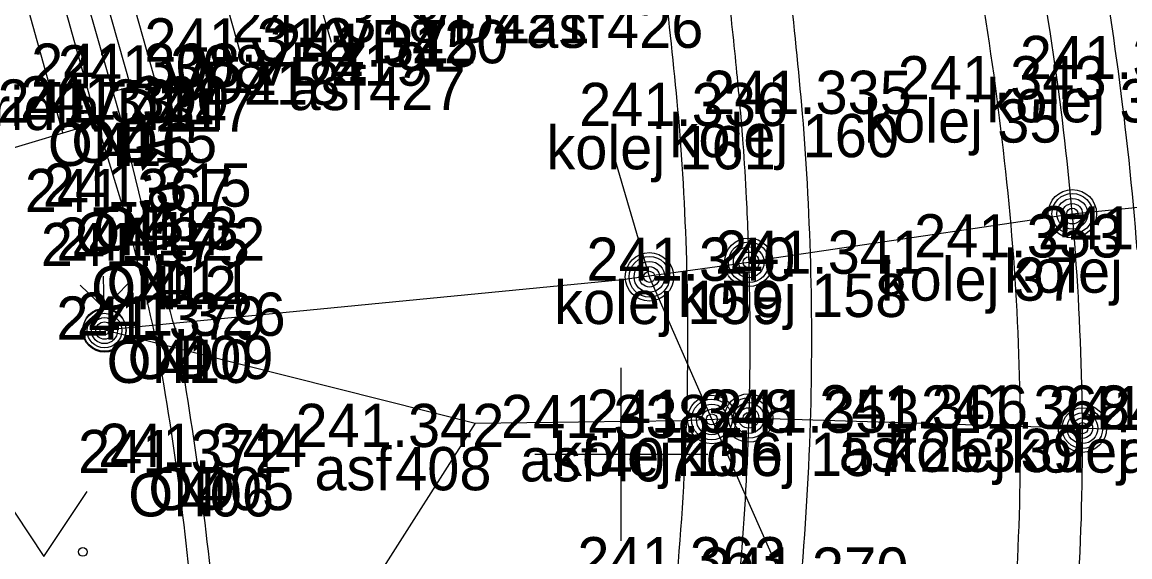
# Model space of a CAD drawing. Extents: x -599098 to -598820, y -1159597 to -1158744.
# Drawn here: x -598906.93 to -598894.12, y -1159351.19 to -1159345 of the extents above; entities that cross this region are included whole.
import ezdxf

# ---------------------------------------------------------------- set-up
doc = ezdxf.new("R2010")
doc.units = 0
for name, color, linetype in [('body', 7, 'Continuous'), ('druh pozemku stromy', 7, 'Continuous'), ('hektometrická síť', 7, 'Continuous'), ('kresba', 7, 'Continuous'), ('kódy bodů', 7, 'Continuous'), ('popisy', 7, 'Continuous'), ('tram_koleje', 7, 'Continuous'), ('tram_osa', 7, 'Continuous'), ('trol_detaily', 7, 'Continuous'), ('trol_převěsy', 7, 'Continuous'), ('trol_troljová stopa', 7, 'Continuous'), ('trol_ved sloupy konzoly', 7, 'Continuous'), ('vodorovné dopravní značení_bílé', 7, 'Continuous'), ('výšky bodů', 7, 'Continuous'), ('značky IS', 7, 'Continuous'), ('čísla bodů', 7, 'Continuous')]:
    doc.layers.add(name, color=color, linetype=linetype)

msp = doc.modelspace()

# ---------------------------------------------------------------- linework, layer by layer
at = {"layer": 'body'}
for p, q in [((-598903.354, -1159345.238), (-598903.354, -1159345.238)), ((-598904.366, -1159345.459), (-598904.366, -1159345.459)), ((-598902.918, -1159345.52), (-598902.918, -1159345.52)), ((-598894.236, -1159345.662), (-598894.236, -1159345.662)), ((-598905.676, -1159345.751), (-598905.676, -1159345.751)), ((-598905.367, -1159345.77), (-598905.367, -1159345.77)), ((-598895.649, -1159345.896), (-598895.649, -1159345.896)), ((-598897.902, -1159346.065), (-598897.902, -1159346.065)), ((-598906.065, -1159346.166), (-598906.065, -1159346.166)), ((-598905.791, -1159346.13), (-598905.791, -1159346.13)), ((-598899.327, -1159346.205), (-598899.327, -1159346.205)), ((-598905.542, -1159347.137), (-598905.542, -1159347.137)), ((-598905.749, -1159347.2), (-598905.749, -1159347.2)), ((-598905.384, -1159347.763), (-598905.384, -1159347.763)), ((-598895.459, -1159347.724), (-598895.459, -1159347.724)), ((-598905.564, -1159347.824), (-598905.564, -1159347.824)), ((-598897.805, -1159347.913), (-598897.805, -1159347.913)), ((-598899.237, -1159347.994), (-598899.237, -1159347.994)), ((-598905.385, -1159348.675), (-598905.385, -1159348.675)), ((-598905.14, -1159348.63), (-598905.14, -1159348.63)), ((-598896.55, -1159349.701), (-598896.55, -1159349.701)), ((-598895.381, -1159349.704), (-598895.381, -1159349.704)), ((-598900.24, -1159349.813), (-598900.24, -1159349.813)), ((-598899.248, -1159349.751), (-598899.248, -1159349.751)), ((-598897.814, -1159349.751), (-598897.814, -1159349.751)), ((-598902.617, -1159349.916), (-598902.617, -1159349.916)), ((-598905.134, -1159350.218), (-598905.134, -1159350.218)), ((-598904.9, -1159350.146), (-598904.9, -1159350.146))]:
    msp.add_line(p, q, dxfattribs=at)
at = {"layer": 'druh pozemku stromy'}
msp.add_lwpolyline([(-598907.18, -1159350.43), (-598906.68, -1159351.18), (-598906.18, -1159350.43)], dxfattribs=at)
msp.add_lwpolyline([(-598907.18, -1159350.43), (-598906.68, -1159351.18), (-598906.18, -1159350.43)], dxfattribs=at)
msp.add_circle((-598906.231, -1159351.129), 0.05, dxfattribs=at)
msp.add_circle((-598906.231, -1159351.129), 0.05, dxfattribs=at)
at = {"layer": 'hektometrická síť'}
for p, q in [((-598900, -1159351), (-598900, -1159349)), ((-598901, -1159350), (-598899, -1159350))]:
    msp.add_line(p, q, dxfattribs=at)
at = {"layer": 'kresba'}
for p, q in [((-598905.676, -1159345.751), (-598907.263, -1159340.087)), ((-598906.065, -1159346.166), (-598907.388, -1159341.438)), ((-598907.153, -1159341.381), (-598905.791, -1159346.13)), ((-598906.46, -1159346.285), (-598907.797, -1159341.508)), ((-598905.676, -1159345.751), (-598905.882, -1159345.81)), ((-598906.065, -1159346.166), (-598909.141, -1159347.095)), ((-598905.749, -1159347.2), (-598906.065, -1159346.166)), ((-598905.791, -1159346.13), (-598905.542, -1159347.137))]:
    msp.add_line(p, q, dxfattribs=at)
for centre, radius, start, end in [((-598877.803, -1159340.469), 28.529, 193.517, 196.6227), ((-598928.971, -1159353.713), 24.118, 12.0576, 15.6673), ((-598936.186, -1159354.477), 31.342, 4.3371, 10.6684), ((-598943.571, -1159355.491), 39.039, 4.9847, 10.1223)]:
    msp.add_arc(centre, radius, start, end, dxfattribs=at)
at = {"layer": 'tram_koleje'}
for centre, radius, start, end in [((-598957.61, -1159351.342), 59.941, 5.05089, 8.00972), ((-598962.061, -1159351.823), 62.985, 5.11744, 7.90196), ((-598930.034, -1159350.401), 36.11, 4.398, 10.9741), ((-598930.08, -1159350.399), 34.724, 4.4175, 11.0015), ((-598929.966, -1159348.675), 32.17, 358.0824, 4.6528), ((-598930.62, -1159348.676), 31.391, 358.0376, 4.5149), ((-598924.431, -1159349.857), 29.05, 356.3663, 4.2104), ((-598930.909, -1159348.603), 31.681, 350.7182, 357.9236), ((-598931.638, -1159348.556), 33.845, 350.8772, 357.9764)]:
    msp.add_arc(centre, radius, start, end, dxfattribs=at)
at = {"layer": 'tram_osa'}
for points in [[(-598908.157, -1159378.609), (-598907.552, -1159377.778), (-598906.868, -1159376.836), (-598906.259, -1159375.995), (-598905.722, -1159375.252), (-598905.236, -1159374.581), (-598903.934, -1159372.775), (-598902.701, -1159371.051), (-598901.52, -1159369.371), (-598900.942, -1159368.531), (-598900.379, -1159367.695), (-598899.817, -1159366.835), (-598899.27, -1159365.964), (-598898.407, -1159364.472), (-598897.213, -1159362.023), (-598896.143, -1159359.185), (-598895.328, -1159356.139), (-598894.957, -1159354.036), (-598894.725, -1159351.774), (-598894.664, -1159349.708), (-598894.744, -1159347.678), (-598894.942, -1159345.779), (-598895.289, -1159343.649), (-598895.717, -1159341.566), (-598895.998, -1159340.38), (-598896.298, -1159339.199), (-598896.678, -1159337.758), (-598897.069, -1159336.322), (-598897.39, -1159335.158), (-598897.753, -1159333.858), (-598898.122, -1159332.54), (-598898.277, -1159331.985), (-598898.513, -1159331.142), (-598898.836, -1159329.985), (-598899.092, -1159329.068)], [(-598901.994, -1159329.852), (-598901.845, -1159330.39), (-598901.631, -1159331.17), (-598901.437, -1159331.875), (-598901.198, -1159332.751), (-598900.91, -1159333.821), (-598900.692, -1159334.638), (-598900.522, -1159335.294), (-598900.329, -1159336.063), (-598900.132, -1159336.868), (-598899.889, -1159337.918), (-598899.746, -1159338.571), (-598899.547, -1159339.551), (-598899.39, -1159340.382), (-598899.195, -1159341.532), (-598899.02, -1159342.683), (-598898.837, -1159344.035), (-598898.771, -1159344.588), (-598898.665, -1159345.59), (-598898.593, -1159346.409), (-598898.554, -1159347.04), (-598898.521, -1159347.953), (-598898.531, -1159349.751), (-598898.642, -1159351.517), (-598898.931, -1159353.817), (-598899.252, -1159355.498), (-598899.926, -1159358.17), (-598900.833, -1159360.806), (-598901.398, -1159362.161), (-598902.424, -1159364.327), (-598904.147, -1159367.423), (-598905.388, -1159369.399), (-598906.458, -1159371.007), (-598907.174, -1159372.046), (-598907.418, -1159372.398), (-598907.811, -1159372.961), (-598908.189, -1159373.5), (-598908.527, -1159373.98), (-598908.94, -1159374.563), (-598909.247, -1159374.993), (-598909.701, -1159375.623), (-598910.021, -1159376.065), (-598910.194, -1159376.303), (-598910.561, -1159376.808)]]:
    msp.add_spline(points, degree=3, dxfattribs=at)
at = {"layer": 'trol_detaily'}
for centre, radius in [((-598894.781, -1159347.219), 0.28), ((-598894.781, -1159347.219), 0.235), ((-598894.781, -1159347.219), 0.178), ((-598894.781, -1159347.219), 0.118), ((-598894.781, -1159347.219), 0.0641), ((-598898.525, -1159347.78), 0.28), ((-598898.525, -1159347.78), 0.235), ((-598898.525, -1159347.78), 0.178), ((-598899.674, -1159347.948), 0.28), ((-598899.674, -1159347.948), 0.235), ((-598899.674, -1159347.948), 0.178), ((-598898.525, -1159347.78), 0.118), ((-598898.525, -1159347.78), 0.0641), ((-598899.674, -1159347.948), 0.118), ((-598899.674, -1159347.948), 0.0641), ((-598898.952, -1159349.597), 0.28), ((-598898.526, -1159349.58), 0.28), ((-598898.952, -1159349.597), 0.235), ((-598898.952, -1159349.597), 0.178), ((-598898.526, -1159349.58), 0.235), ((-598898.526, -1159349.58), 0.178), ((-598894.664, -1159349.698), 0.28), ((-598898.952, -1159349.597), 0.118), ((-598898.952, -1159349.597), 0.0641), ((-598898.526, -1159349.58), 0.118), ((-598898.526, -1159349.58), 0.0641), ((-598894.664, -1159349.698), 0.235), ((-598894.664, -1159349.698), 0.178), ((-598894.664, -1159349.698), 0.118), ((-598894.664, -1159349.698), 0.0641)]:
    msp.add_circle(centre, radius, dxfattribs=at)
at = {"layer": 'trol_převěsy'}
for p, q in [((-598894.781, -1159347.218), (-598891.512, -1159346.899)), ((-598898.23, -1159347.73), (-598894.781, -1159347.218)), ((-598899.99, -1159347.98), (-598898.525, -1159347.779)), ((-598898.525, -1159347.779), (-598898.23, -1159347.73)), ((-598905.98, -1159348.56), (-598899.99, -1159347.98)), ((-598905.98, -1159348.56), (-598901.69, -1159349.64)), ((-598899.3, -1159349.61), (-598898.54, -1159349.58)), ((-598898.54, -1159349.58), (-598894.25, -1159349.71)), ((-598901.69, -1159349.64), (-598906.25, -1159356.79)), ((-598901.69, -1159349.64), (-598899.3, -1159349.61)), ((-598894.25, -1159349.71), (-598891.79, -1159349.74))]:
    msp.add_line(p, q, dxfattribs=at)
at = {"layer": 'trol_troljová stopa'}
for p, q in [((-598899.67, -1159347.96), (-598900.1, -1159346.487)), ((-598898.95, -1159349.6), (-598899.67, -1159347.96)), ((-598896.7, -1159354.66), (-598898.95, -1159349.6))]:
    msp.add_line(p, q, dxfattribs=at)
at = {"layer": 'trol_ved sloupy konzoly'}
for q in [(-598906.259, -1159348.044), (-598905.99, -1159347.939), (-598905.698, -1159348.018)]:
    msp.add_line((-598905.984, -1159348.311), q, dxfattribs=at)
msp.add_circle((-598905.98, -1159348.56), 0.248, dxfattribs=at)
at = {"layer": 'vodorovné dopravní značení_bílé'}
for p, q in [((-598903.354, -1159345.238), (-598904.741, -1159340.325)), ((-598904.366, -1159345.497), (-598905.753, -1159340.584)), ((-598905.367, -1159345.77), (-598906.754, -1159340.857))]:
    msp.add_line(p, q, dxfattribs=at)
at = {"layer": 'značky IS'}
for radius in [0.25, 0.2, 0.15, 0.1, 0.05]:
    msp.add_circle((-598905.98, -1159348.57), radius, dxfattribs=at)

# ---------------------------------------------------------------- texts
at = {"layer": 'kódy bodů'}
for s, p in [('VDZ', (-598902.4, -1159345.249)), ('asf', (-598901.098, -1159345.301)), ('VDZ', (-598903.341, -1159345.479)), ('VDZ', (-598904.274, -1159345.738)), ('VDZ', (-598905.286, -1159345.959)), ('asf', (-598903.851, -1159346.02)), ('pridla', (-598907.662, -1159346.251)), ('kolej', (-598895.776, -1159346.162)), ('VDZ', (-598906.287, -1159346.27)), ('kolej', (-598897.189, -1159346.396)), ('kolej', (-598899.442, -1159346.565)), ('ON', (-598906.635, -1159346.666)), ('OD', (-598906.363, -1159346.63)), ('kolej', (-598900.867, -1159346.705)), ('OD', (-598906.114, -1159347.637)), ('ON', (-598906.319, -1159347.7)), ('kolej', (-598895.57, -1159348.132)), ('OD', (-598905.956, -1159348.263)), ('kolej', (-598896.999, -1159348.224)), ('ON', (-598906.134, -1159348.324)), ('kolej', (-598899.345, -1159348.413)), ('kolej', (-598900.777, -1159348.494)), ('ON', (-598905.955, -1159349.175)), ('OD', (-598905.712, -1159349.13)), ('asf', (-598897.483, -1159350.201)), ('kolej', (-598896.921, -1159350.204)), ('kolej', (-598895.488, -1159350.212)), ('asf', (-598894.248, -1159350.215)), ('asf', (-598901.173, -1159350.313)), ('kolej', (-598900.788, -1159350.251)), ('kolej', (-598899.354, -1159350.251)), ('asf', (-598903.55, -1159350.416)), ('ON', (-598905.704, -1159350.718)), ('OD', (-598905.472, -1159350.646))]:
    msp.add_text(s, height=0.5, dxfattribs=at).set_placement(p)
at = {"layer": 'popisy'}
msp.add_text('k.o.', height=0.5, rotation=283.8889, dxfattribs=at).set_placement((-598905.621, -1159346.402))
at = {"layer": 'výšky bodů'}
for s, p in [('241.318', (-598904.506, -1159345.238)), ('241.312', (-598905.518, -1159345.459)), ('241.315', (-598904.07, -1159345.52)), ('241.345', (-598895.388, -1159345.662)), ('241.308', (-598906.828, -1159345.751)), ('241.308', (-598906.519, -1159345.77)), ('241.343', (-598896.801, -1159345.896)), ('241.335', (-598899.054, -1159346.065)), ('241.337', (-598907.217, -1159346.166)), ('241.300', (-598906.957, -1159346.13)), ('241.336', (-598900.487, -1159346.205)), ('241.315', (-598906.694, -1159347.137)), ('241.367', (-598906.901, -1159347.2)), ('241.355', (-598895.182, -1159347.632)), ('241.322', (-598906.536, -1159347.763)), ('241.353', (-598896.611, -1159347.724)), ('241.375', (-598906.716, -1159347.824)), ('241.340', (-598900.403, -1159347.994)), ('241.341', (-598898.913, -1159347.913)), ('241.379', (-598906.537, -1159348.675)), ('241.326', (-598906.3, -1159348.63)), ('241.366', (-598897.71, -1159349.701)), ('241.368', (-598896.533, -1159349.704)), ('241.338', (-598901.392, -1159349.813)), ('241.348', (-598900.4, -1159349.751)), ('241.353', (-598898.966, -1159349.751)), ('241.371', (-598895.056, -1159349.712)), ('241.376', (-598894.475, -1159349.715)), ('241.342', (-598903.769, -1159349.916)), ('241.344', (-598906.052, -1159350.146)), ('241.372', (-598906.286, -1159350.218)), ('241.363', (-598900.508, -1159351.457)), ('241.370', (-598899.094, -1159351.577))]:
    msp.add_text(s, height=0.5, dxfattribs=at).set_placement(p)
at = {"layer": 'čísla bodů'}
for s, p in [('421', (-598901.48, -1159345.249)), ('426', (-598900.165, -1159345.301)), ('420', (-598902.421, -1159345.479)), ('419', (-598903.354, -1159345.738)), ('418', (-598904.366, -1159345.959)), ('427', (-598902.918, -1159346.02)), ('36', (-598894.236, -1159346.162)), ('434', (-598905.676, -1159346.251)), ('417', (-598905.367, -1159346.27)), ('35', (-598895.649, -1159346.396)), ('160', (-598897.902, -1159346.565)), ('416', (-598906.065, -1159346.666)), ('415', (-598905.791, -1159346.63)), ('161', (-598899.327, -1159346.705)), ('413', (-598905.542, -1159347.637)), ('414', (-598905.749, -1159347.7)), ('411', (-598905.384, -1159348.263)), ('37', (-598895.459, -1159348.224)), ('412', (-598905.564, -1159348.324)), ('158', (-598897.805, -1159348.413)), ('159', (-598899.237, -1159348.494)), ('410', (-598905.385, -1159349.175)), ('409', (-598905.14, -1159349.13)), ('253', (-598896.55, -1159350.201)), ('39', (-598895.381, -1159350.204)), ('407', (-598900.24, -1159350.313)), ('156', (-598899.248, -1159350.251)), ('157', (-598897.814, -1159350.251)), ('408', (-598902.617, -1159350.416)), ('406', (-598905.134, -1159350.718)), ('405', (-598904.9, -1159350.646))]:
    msp.add_text(s, height=0.5, dxfattribs=at).set_placement(p)

doc.saveas('drawing.dxf')
